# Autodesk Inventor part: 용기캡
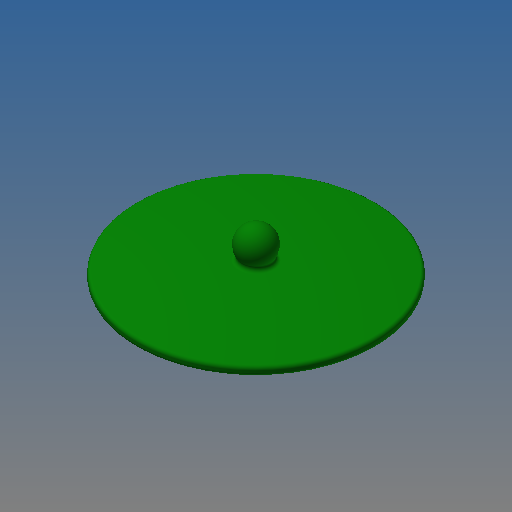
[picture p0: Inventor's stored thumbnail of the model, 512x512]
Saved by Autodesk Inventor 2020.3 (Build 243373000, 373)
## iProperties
Created: 2018-01
Part Number: 용기캡
Material: ABS 플라스틱
Document SubType Name: Modeling
Designer: mduedu
Density: 1 g/cm^3
Appearance: 진녹색
Author: mduedu
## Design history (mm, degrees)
sketch "스케치1"
  geometry: L1 (-35, 2.5)-(0, 2.5); L2 (0, 5)-(0, 0); L3 (0, 0)-(-35, 0); L4 (-35, 0)-(-35, 2.5); L5 (-31, 0)-(-29, 0); L6 (-29, 0)-(-29, -2); L7 (-29, -2)-(-31, -2); L8 (-31, -2)-(-31, 0); A1 r 246.25 centre (0, -241.25) between (0, 5) and (-35, 2.5); 1 further point
  constraints: 16 end point, 4 parallel, 2 horizontal, 2 perpendicular, 2 point on circle, 1 centre point, 1 coincident, 1 midpoint, 1 point on line, 1 vertical alignment
  dimensions: "d2" = 70 diameter of L4 L2; "d3" = 5 distance from line of L2.start L3; "d4" = 2.5 distance of L3.end L1.start; "d5" = 4 distance between parallel lines of L8 L4; "d6" = 2 distance of L6.end L7.end; "d7" = 2 distance between parallel lines of L7 L3
revolve "회전1" sketch "스케치1" stored, may be unused: angle "d8" = 90 deg
chamfer "모따기1" distance "d9" = 0.5; stored, may be unused: second distance "d10" = 2, angle "d11" = 45 deg
fillet "모깎기1" dims "d12" = 1
fillet "모깎기2" dims "d13" = 1
sketch "스케치2"
  geometry: L1 (-30.5, -2)-(-31, -1.5) reference; L2 (-31, -1.5)-(-31, 0) reference; L3 (-31, 0)-(-34, 0) reference; L4 (-35, 1)-(-35, 1.632) reference; L5 (35, 1.632)-(35, 1) reference; L6 (34, 0)-(31, 0) reference; L7 (31, 0)-(31, -1.5) reference; L8 (31, -1.5)-(30.5, -2) reference; L9 (30.5, -2)-(29, -2) reference; L10 (29, -2)-(29, -1) reference; L11 (28, 0)-(-28, 0) reference; L12 (-29, -1)-(-29, -2) reference; L13 (-29, -2)-(-30.5, -2) reference; L14 (0, 14)-(0, 4); A1 r 1 centre (-34, 1) between (-35, 1) and (-34, 0) reference; A2 r 1 centre (-34, 1.632) between (-34.139, 2.622) and (-35, 1.632) reference; A3 r 246.25 centre (0, -241.25) between (34.139, 2.622) and (-34.139, 2.622) reference; A4 r 1 centre (34, 1.632) between (35, 1.632) and (34.139, 2.622) reference; A5 r 1 centre (34, 1) between (34, 0) and (35, 1) reference; A6 r 1 centre (28, -1) between (29, -1) and (28, 0) reference; A7 r 1 centre (-28, -1) between (-28, 0) and (-29, -1) reference; A8 r 5 centre (0, 9) between (0, 14) and (0, 4); 3 further points
  constraints: 2 end point, 2 midpoint, 2 point on circle, 1 centre point, 1 coincident, 1 perpendicular, 1 point on line, 1 vertical alignment
  dimensions: "d14" = 10 diameter of A8; "d16" = 9 distance of A8.centre point (0, 0)
revolve "회전2" sketch "스케치2" stored, may be unused: angle "d17" = 90 deg
fillet "모깎기3" dims "d18" = 1
node "솔리드1"
node "절단 모서리 투영1"
